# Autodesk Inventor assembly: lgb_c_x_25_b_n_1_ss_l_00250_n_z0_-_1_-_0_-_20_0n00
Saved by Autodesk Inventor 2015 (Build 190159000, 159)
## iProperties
Created: 2022-04
Part Number: lgb_c_x_25_b_n_1_ss_l_00250_n_z0_-_1_-_0_-_20_0n00
Checked By: TraceParts S.A.
Catalog Web Link: www.traceparts.com
Document SubType Name: Assembly
Designer: TraceParts
Company: TraceParts S.A.
Author: TraceParts
REFERENCE: LGB C X 25 B N 1 SS L 00250 N Z0 - 1 - 0 - 20.0N
NOTE: Schiene: LGBR 25 L 00250 N 1 - 0 - 20.0N
QUANTITY1: 1
SUPPLIER: NTN-SNR Roulements
DESIGN: Linearführungen LGBCX - B
NOTE1: Führungswagen: LGB C X 25 B N SS N Z0-N
QUANTITY: 1
TraceParts.PartNumber: 34-17012016-094655
TraceParts.PartTitle: Linearführungen LGBCX - B
TraceParts.InstanceId: 34-17012016-0946553VOTEDBU3YMNPI81DR9SWMD3S
TraceParts.PartVersion: 1.1.5
TraceParts.PartLanguage: de
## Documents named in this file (4)
- C:\TPO v2\SharedFS\Outgoing\lgb_c_x_25_b_n_1_ss_l_00250_n_z0_-_1_-_0_-_20_0n00.iam
- C:\TPO v2\SharedFS\Outgoing\lgb_c_x_25_b_n_1_ss_l_00250_n_z0_-_1_-_0_-_20_0n00_01.ipt
- C:\TPO v2\SharedFS\Outgoing\lgb_c_x_25_b_n_1_ss_l_00250_n_z0_-_1_-_0_-_20_0n00_02.ipt
- C:\TPO v2\SharedFS\Outgoing\lgb_c_x_25_b_n_1_ss_l_00250_n_z0_-_1_-_0_-_20_0n00_03.ipt
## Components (3 placed, 3 different names)
1. lgb_c_x_25_b_n_1_ss_l_00250_n_z0_-_1_-_0_-_20_0n00_01:1
2. lgb_c_x_25_b_n_1_ss_l_00250_n_z0_-_1_-_0_-_20_0n00_02:1
3. lgb_c_x_25_b_n_1_ss_l_00250_n_z0_-_1_-_0_-_20_0n00_03:1
